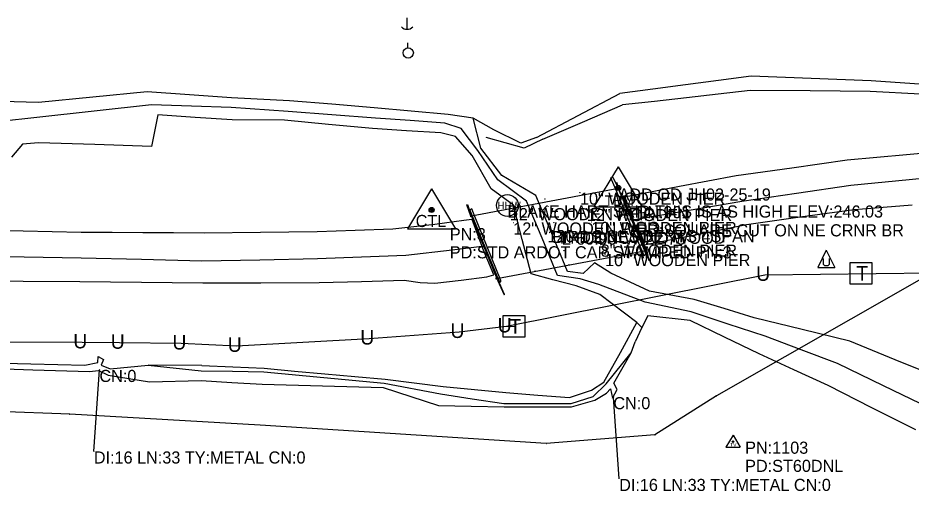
# Model space of a CAD drawing. Extents: x 1939239 to 1943096, y 531224 to 537447.
# Drawn here: x 1940668.9 to 1941037.4, y 534669 to 534864.3 of the extents above; entities that cross this region are included whole.
import ezdxf

# ---------------------------------------------------------------- set-up
doc = ezdxf.new("R2010")
doc.units = 0
for name, color, linetype in [('Default', 7, 'Continuous'), ('S_BRIDGE', 7, 'Continuous'), ('S_BRIDGE_ANNOT', 7, 'Continuous'), ('S_CROSS_DRAIN', 7, 'Continuous'), ('S_CROSS_DRAIN_ANNOT', 7, 'Continuous'), ('S_DITCHLINE', 7, 'Continuous'), ('S_DRG_PT_SYM', 7, 'Continuous'), ('S_EDGE_PAVEMENT', 7, 'Continuous'), ('S_HIST_HIGH_WATER', 7, 'Continuous'), ('S_HIST_HIGH_WATER_ANNOT', 7, 'Continuous'), ('S_MISC_STRUCTURES_ANNOT', 7, 'Continuous'), ('S_MSC_PT_SYM', 7, 'Continuous'), ('S_PAVEMENT_CROWN', 7, 'Continuous'), ('S_PRIMARY_CTL', 7, 'Continuous'), ('S_PRIMARY_CTL_ANNOT', 7, 'Continuous'), ('S_SECONDARY_CTL', 7, 'Continuous'), ('S_SECONDARY_CTL_ANNOT', 7, 'Continuous'), ('S_STR_PT_SYM', 7, 'Continuous'), ('S_SURVEY_TEXT_ANNOT', 7, 'Continuous'), ('S_TELEPHONE_UTILITIES', 7, 'Continuous'), ('S_UNDERGROUND_CABLE', 7, 'Continuous'), ('S_UTILITY_POLE', 7, 'Continuous'), ('S_UTL_PT_SYM', 7, 'Continuous'), ('S_WALL', 7, 'Continuous'), ('S_WATER_UTILITIES', 7, 'Continuous')]:
    doc.layers.add(name, color=color, linetype=linetype)

msp = doc.modelspace()

# ---------------------------------------------------------------- linework, layer by layer
at = {"layer": 'S_BRIDGE'}
for p, q in [((1940916.7, 534793.93), (1940855.99, 534782.52)), ((1940928.01, 534768.34), (1940916.7, 534793.93)), ((1940855.99, 534782.52), (1940866.42, 534756.81)), ((1940866.42, 534756.81), (1940928.01, 534768.34))]:
    msp.add_line(p, q, dxfattribs=at)
at = {"layer": 'S_CROSS_DRAIN'}
for p, q in [((1940700.2, 534685.38), (1940702.51, 534719.04)), ((1940916.92, 534674.06), (1940914.53, 534707.81))]:
    msp.add_line(p, q, dxfattribs=at)
at = {"layer": 'S_DITCHLINE'}
for points in [[(1941356.72, 534832.94), (1941356.86, 534833.91), (1941338.36, 534833.68), (1941319.86, 534833.44), (1941298.62, 534833.2), (1941277.38, 534832.97), (1941256.04, 534833.57), (1941234.71, 534834.18), (1941214.38, 534834.56), (1941194.04, 534834.93), (1941175.23, 534835.53), (1941156.41, 534836.12), (1941133.85, 534837.32), (1941111.3, 534838.52), (1941087.89, 534836.93), (1941064.48, 534835.33), (1941042.69, 534836.83), (1941020.9, 534838.32), (1940996.16, 534839.27), (1940971.42, 534840.22), (1940957.88, 534838.44), (1940944.34, 534836.67), (1940930.79, 534834.89), (1940917.25, 534833.11)], [(1941049.66, 534715.63), (1941030.84, 534723.24), (1941012.02, 534730.85), (1940992.35, 534735.7), (1940972.67, 534740.54), (1940960.27, 534744.33), (1940947.88, 534748.11), (1940929.43, 534751.52), (1940913.49, 534758.92), (1940906.72, 534763.16), (1940902.02, 534758.85), (1940895.66, 534759.68), (1940889.09, 534775.36), (1940882.53, 534791.03), (1940868.57, 534799.24), (1940859.9, 534810.49), (1940856.63, 534822.99), (1940846.33, 534824.51), (1940831.06, 534825.88), (1940815.8, 534827.24), (1940798.32, 534828.7), (1940780.85, 534830.15), (1940757, 534831.31), (1940739.62, 534832.53), (1940722.24, 534833.75), (1940699.8, 534831.6), (1940677.37, 534829.44), (1940662.29, 534829.82)], [(1940882.86, 534814.91), (1940900.06, 534824.01), (1940917.25, 534833.11)], [(1941356.66, 534832.31), (1941338.01, 534831.38), (1941319.37, 534830.45), (1941298.07, 534830.31), (1941276.77, 534830.18), (1941255.95, 534830.68), (1941235.14, 534831.17), (1941214.28, 534831.69), (1941193.41, 534832.21), (1941174.87, 534832.43), (1941156.32, 534832.65), (1941133.65, 534833.25), (1941110.99, 534833.85), (1941086.48, 534832.82), (1941061.97, 534831.78), (1941041.25, 534832.89), (1941020.53, 534834.01), (1940995.73, 534834.15), (1940970.92, 534834.29), (1940957.78, 534832.82), (1940944.63, 534831.35), (1940931.48, 534829.87), (1940918.33, 534828.4)], [(1941045.02, 534703.25), (1941026, 534712.47), (1941006.97, 534721.69), (1940992.06, 534727.32), (1940977.15, 534732.95), (1940961.91, 534737.97), (1940946.67, 534742.99), (1940927.62, 534747.04), (1940908.47, 534754.3), (1940900.87, 534756.68), (1940891.53, 534758.05), (1940885.14, 534773.37), (1940878.74, 534788.7), (1940866.82, 534797.46), (1940858.55, 534809.6), (1940851.74, 534818.65), (1940844.96, 534820.87), (1940830.66, 534821.93), (1940816.36, 534822.99), (1940798.33, 534824.31), (1940780.3, 534825.62), (1940756.86, 534827.33), (1940740.45, 534827.88), (1940724.04, 534828.42), (1940700.37, 534825.85), (1940676.71, 534823.27), (1940661.7, 534821.6)], [(1940885.36, 534814.2), (1940901.85, 534821.3), (1940918.33, 534828.4)], [(1941039.25, 534694.23), (1941021.19, 534703.39), (1941003.13, 534712.55), (1940988.93, 534719.08), (1940974.73, 534725.61), (1940960.44, 534732.49), (1940946.16, 534739.38), (1940928.75, 534741.4), (1940926.3, 534736.57), (1940924.19, 534738.53), (1940908.97, 534750.13), (1940899.12, 534753.8), (1940889.59, 534756.15), (1940880.57, 534758.73), (1940876.97, 534772.89), (1940873.38, 534787.05), (1940864.14, 534793.79), (1940856.34, 534807.59), (1940849.35, 534815.33), (1940843.39, 534816.83), (1940829.25, 534817.73), (1940815.11, 534818.63), (1940796.95, 534820.39), (1940778.79, 534822.15), (1940757.29, 534822.18), (1940741.96, 534823.26), (1940726.62, 534824.34), (1940724.02, 534811.28), (1940700.67, 534812.03), (1940677.33, 534812.78), (1940670.81, 534812.16), (1940666.3, 534806.81)], [(1940865.25, 534818.17), (1940856.63, 534822.99)], [(1940882.86, 534814.91), (1940876.29, 534812.65), (1940865.25, 534818.17)], [(1940885.36, 534814.2), (1940877.76, 534810.56), (1940862.03, 534814.92)], [(1940910.66, 534713.92), (1940917.42, 534726.23), (1940924.19, 534738.53)], [(1940926.3, 534736.57), (1940923.48, 534730.55)], [(1940651.98, 534722.03), (1940674.22, 534721.5), (1940696.47, 534720.96), (1940701.9, 534722.08), (1940702.01, 534724.54), (1940704.16, 534723.31), (1940703.16, 534720.94), (1940706.98, 534719.43), (1940722.63, 534720.97), (1940744.51, 534718.71), (1940757.43, 534718.48), (1940770.35, 534718.25), (1940795.15, 534715.93), (1940819.95, 534713.62), (1940843.22, 534709.12), (1940856.28, 534707.16), (1940869.33, 534705.2), (1940883.22, 534705.16), (1940897.11, 534705.11), (1940906.19, 534708.08), (1940911.56, 534713.24), (1940921.89, 534726.14), (1940923.48, 534730.55)], [(1940914.68, 534713.52), (1940921.89, 534726.14)], [(1940651.66, 534719.94), (1940675, 534719.13), (1940698.35, 534718.32), (1940702.14, 534718.83), (1940706.05, 534716.91), (1940723.16, 534714.1), (1940744.53, 534714.6), (1940757.07, 534713.85), (1940769.61, 534713.1), (1940794.57, 534712.45), (1940819.52, 534711.8), (1940842.41, 534704.34), (1940855.93, 534704.08), (1940869.44, 534703.81), (1940883.36, 534703.77), (1940897.29, 534703.73), (1940906.9, 534706.49), (1940911.72, 534709.49), (1940913.39, 534711.19), (1940914.17, 534707.43), (1940916.06, 534711.01), (1940914.68, 534713.52)], [(1940744.69, 534720.82), (1940722.63, 534720.97)], [(1940744.69, 534720.82), (1940757.58, 534720.26), (1940770.47, 534719.7), (1940782.95, 534718.57), (1940795.43, 534717.43), (1940807.91, 534716.3), (1940820.39, 534715.17), (1940844.25, 534712.15), (1940857.22, 534710.9), (1940870.2, 534709.66), (1940883.31, 534708.67), (1940896.42, 534707.68), (1940905.57, 534710.7), (1940910.66, 534713.92)]]:
    msp.add_lwpolyline(points, dxfattribs=at)
at = {"layer": 'S_DRG_PT_SYM'}
for points in [[(1940702.51, 534719.04), (1940702.51, 534719.09), (1940702.51, 534719.04), (1940702.46, 534719.04), (1940702.51, 534719.04), (1940702.51, 534718.99), (1940702.51, 534719.04), (1940702.56, 534719.04)], [(1940914.53, 534707.81), (1940914.53, 534707.86), (1940914.53, 534707.81), (1940914.48, 534707.81), (1940914.53, 534707.81), (1940914.53, 534707.76), (1940914.53, 534707.81), (1940914.58, 534707.81)], [(1940700.2, 534685.38), (1940700.2, 534685.43), (1940700.2, 534685.38), (1940700.15, 534685.38), (1940700.2, 534685.38), (1940700.2, 534685.33), (1940700.2, 534685.38), (1940700.25, 534685.38)], [(1940916.92, 534674.06), (1940916.92, 534674.11), (1940916.92, 534674.06), (1940916.87, 534674.06), (1940916.92, 534674.06), (1940916.92, 534674.01), (1940916.92, 534674.06), (1940916.97, 534674.06)]]:
    msp.add_lwpolyline(points, dxfattribs=at)
at = {"layer": 'S_EDGE_PAVEMENT'}
for points in [[(1940918.46, 534790.36), (1940941.8, 534794.81), (1940965.15, 534799.25), (1940988.1, 534802.49), (1941011.04, 534805.72), (1941035.48, 534807.92), (1941059.93, 534810.12)], [(1940918.46, 534790.36), (1940922.58, 534780.98)], [(1940927.18, 534770.6), (1940948.3, 534774.85), (1940969.42, 534779.09), (1940991.65, 534782.15), (1941013.88, 534785.21), (1941037.83, 534787.17)], [(1940647.14, 534776.84), (1940671.09, 534776.39), (1940695.04, 534775.95), (1940707.71, 534775.87), (1940720.38, 534775.8), (1940733.06, 534775.73), (1940745.73, 534775.66), (1940769.02, 534775.88), (1940792.32, 534776.1), (1940807.94, 534776.69), (1940823.56, 534777.27), (1940840.91, 534779.15), (1940852.87, 534780.9), (1940856.11, 534781.19)], [(1940856.11, 534781.19), (1940860.29, 534770.05)], [(1940927.18, 534770.6), (1940922.58, 534780.98)], [(1940865.21, 534758.31), (1940860.29, 534770.05)], [(1940647.55, 534755.91), (1940671.01, 534755.72), (1940694.46, 534755.53), (1940707.14, 534755.39), (1940719.83, 534755.24), (1940732.52, 534755.09), (1940745.2, 534754.95), (1940769.16, 534755.02), (1940793.12, 534755.09), (1940810.66, 534755.57), (1940828.2, 534756.05), (1940834.85, 534755.15), (1940840.83, 534754.78), (1940851.7, 534756.09), (1940862.27, 534757.47), (1940865.21, 534758.31)]]:
    msp.add_lwpolyline(points, dxfattribs=at)
at = {"layer": 'S_HIST_HIGH_WATER'}
msp.add_circle((1940870.81, 534786.91), 4.5, dxfattribs=at)
at = {"layer": 'S_MSC_PT_SYM'}
for points in [[(1940900.75, 534792.23), (1940900.75, 534792.28), (1940900.75, 534792.23), (1940900.7, 534792.23), (1940900.75, 534792.23), (1940900.75, 534792.18), (1940900.75, 534792.23), (1940900.8, 534792.23)], [(1940886.32, 534789.62), (1940886.32, 534789.67), (1940886.32, 534789.62), (1940886.27, 534789.62), (1940886.32, 534789.62), (1940886.32, 534789.57), (1940886.32, 534789.62), (1940886.37, 534789.62)], [(1940871.83, 534785.81), (1940871.83, 534785.86), (1940871.83, 534785.81), (1940871.78, 534785.81), (1940871.83, 534785.81), (1940871.83, 534785.76), (1940871.83, 534785.81), (1940871.88, 534785.81)], [(1940887.61, 534786.36), (1940887.61, 534786.41), (1940887.61, 534786.36), (1940887.56, 534786.36), (1940887.61, 534786.36), (1940887.61, 534786.31), (1940887.61, 534786.36), (1940887.66, 534786.36)], [(1940903.56, 534785.47), (1940903.56, 534785.52), (1940903.56, 534785.47), (1940903.51, 534785.47), (1940903.56, 534785.47), (1940903.56, 534785.42), (1940903.56, 534785.47), (1940903.61, 534785.47)], [(1940873.23, 534779.89), (1940873.23, 534779.94), (1940873.23, 534779.89), (1940873.18, 534779.89), (1940873.23, 534779.89), (1940873.23, 534779.84), (1940873.23, 534779.89), (1940873.28, 534779.89)], [(1940890.02, 534779.93), (1940890.02, 534779.98), (1940890.02, 534779.93), (1940889.97, 534779.93), (1940890.02, 534779.93), (1940890.02, 534779.88), (1940890.02, 534779.93), (1940890.07, 534779.93)], [(1940905.43, 534780.14), (1940905.43, 534780.19), (1940905.43, 534780.14), (1940905.38, 534780.14), (1940905.43, 534780.14), (1940905.43, 534780.09), (1940905.43, 534780.14), (1940905.48, 534780.14)], [(1940887.33, 534776.75), (1940887.33, 534776.8), (1940887.33, 534776.75), (1940887.28, 534776.75), (1940887.33, 534776.75), (1940887.33, 534776.7), (1940887.33, 534776.75), (1940887.38, 534776.75)], [(1940889.3, 534776.41), (1940889.3, 534776.46), (1940889.3, 534776.41), (1940889.25, 534776.41), (1940889.3, 534776.41), (1940889.3, 534776.36), (1940889.3, 534776.41), (1940889.35, 534776.41)], [(1940891.27, 534776.07), (1940891.27, 534776.12), (1940891.27, 534776.07), (1940891.22, 534776.07), (1940891.27, 534776.07), (1940891.27, 534776.02), (1940891.27, 534776.07), (1940891.32, 534776.07)], [(1940891.83, 534774.13), (1940891.83, 534774.18), (1940891.83, 534774.13), (1940891.78, 534774.13), (1940891.83, 534774.13), (1940891.83, 534774.08), (1940891.83, 534774.13), (1940891.88, 534774.13)], [(1940893.24, 534775.72), (1940893.24, 534775.77), (1940893.24, 534775.72), (1940893.19, 534775.72), (1940893.24, 534775.72), (1940893.24, 534775.67), (1940893.24, 534775.72), (1940893.29, 534775.72)], [(1940875.8, 534773.26), (1940875.8, 534773.31), (1940875.8, 534773.26), (1940875.75, 534773.26), (1940875.8, 534773.26), (1940875.8, 534773.21), (1940875.8, 534773.26), (1940875.85, 534773.26)], [(1940908.08, 534773.63), (1940908.08, 534773.68), (1940908.08, 534773.63), (1940908.03, 534773.63), (1940908.08, 534773.63), (1940908.08, 534773.58), (1940908.08, 534773.63), (1940908.13, 534773.63)], [(1940909.31, 534770.77), (1940909.31, 534770.82), (1940909.31, 534770.77), (1940909.26, 534770.77), (1940909.31, 534770.77), (1940909.31, 534770.72), (1940909.31, 534770.77), (1940909.36, 534770.77)], [(1940878.13, 534768.21), (1940878.13, 534768.26), (1940878.13, 534768.21), (1940878.08, 534768.21), (1940878.13, 534768.21), (1940878.13, 534768.16), (1940878.13, 534768.21), (1940878.18, 534768.21)], [(1940894.13, 534768.27), (1940894.13, 534768.32), (1940894.13, 534768.27), (1940894.08, 534768.27), (1940894.13, 534768.27), (1940894.13, 534768.22), (1940894.13, 534768.27), (1940894.18, 534768.27)], [(1940911.1, 534766.85), (1940911.1, 534766.9), (1940911.1, 534766.85), (1940911.05, 534766.85), (1940911.1, 534766.85), (1940911.1, 534766.8), (1940911.1, 534766.85), (1940911.15, 534766.85)], [(1940880.47, 534762.81), (1940880.47, 534762.86), (1940880.47, 534762.81), (1940880.42, 534762.81), (1940880.47, 534762.81), (1940880.47, 534762.76), (1940880.47, 534762.81), (1940880.52, 534762.81)], [(1940882.23, 534759.85), (1940882.23, 534759.9), (1940882.23, 534759.85), (1940882.18, 534759.85), (1940882.23, 534759.85), (1940882.23, 534759.8), (1940882.23, 534759.85), (1940882.28, 534759.85)], [(1940896.15, 534762.45), (1940896.15, 534762.5), (1940896.15, 534762.45), (1940896.1, 534762.45), (1940896.15, 534762.45), (1940896.15, 534762.4), (1940896.15, 534762.45), (1940896.2, 534762.45)]]:
    msp.add_lwpolyline(points, dxfattribs=at)
at = {"layer": 'S_PAVEMENT_CROWN'}
for points in [[(1940922.58, 534780.98), (1940945.02, 534784.82), (1940967.46, 534788.66), (1940990.01, 534791.94), (1941012.55, 534795.22), (1941036.52, 534797.59), (1941060.48, 534799.96)], [(1940647.87, 534765.97), (1940671.43, 534765.66), (1940694.99, 534765.34), (1940719.89, 534764.69), (1940744.8, 534764.04), (1940768.62, 534764.51), (1940792.45, 534764.97), (1940810.66, 534765.67), (1940828.88, 534766.37), (1940847.99, 534768.6), (1940860.29, 534770.05)]]:
    msp.add_lwpolyline(points, dxfattribs=at)
at = {"layer": 'S_PRIMARY_CTL'}
for p, q in [((1940916.55, 534802.84), (1940906.52, 534786.33)), ((1940916.55, 534802.84), (1940926.38, 534786.33)), ((1940839.56, 534793.77), (1940829.53, 534777.26)), ((1940839.56, 534793.77), (1940849.39, 534777.26)), ((1940906.52, 534786.33), (1940926.38, 534786.33)), ((1940829.53, 534777.26), (1940849.39, 534777.26))]:
    msp.add_line(p, q, dxfattribs=at)
for centre, radius in [((1940916.55, 534794.14), 1.04), ((1940916.55, 534794.14), 0.609), ((1940916.55, 534794.14), 0.344), ((1940839.56, 534785.07), 1.04), ((1940839.56, 534785.07), 0.609), ((1940839.56, 534785.07), 0.344)]:
    msp.add_circle(centre, radius, dxfattribs=at)
at = {"layer": 'S_SECONDARY_CTL'}
for p, q in [((1940963.89, 534692.04), (1940960.88, 534687.09)), ((1940963.89, 534692.04), (1940966.83, 534687.09)), ((1940960.88, 534687.09), (1940966.83, 534687.09))]:
    msp.add_line(p, q, dxfattribs=at)
for radius in [0.311, 0.183, 0.103]:
    msp.add_circle((1940963.89, 534689.43), radius, dxfattribs=at)
at = {"layer": 'S_STR_PT_SYM'}
for points in [[(1940916.7, 534793.93), (1940916.7, 534794.43), (1940916.7, 534793.93), (1940916.2, 534793.93), (1940916.7, 534793.93), (1940916.7, 534793.43), (1940916.7, 534793.93), (1940917.2, 534793.93)], [(1940855.99, 534782.52), (1940855.99, 534783.02), (1940855.99, 534782.52), (1940855.49, 534782.52), (1940855.99, 534782.52), (1940855.99, 534782.02), (1940855.99, 534782.52), (1940856.49, 534782.52)], [(1940928.01, 534768.34), (1940928.01, 534768.84), (1940928.01, 534768.34), (1940927.51, 534768.34), (1940928.01, 534768.34), (1940928.01, 534767.84), (1940928.01, 534768.34), (1940928.51, 534768.34)], [(1940866.42, 534756.81), (1940866.42, 534757.31), (1940866.42, 534756.81), (1940865.92, 534756.81), (1940866.42, 534756.81), (1940866.42, 534756.31), (1940866.42, 534756.81), (1940866.92, 534756.81)]]:
    msp.add_lwpolyline(points, dxfattribs=at)
at = {"layer": 'S_TELEPHONE_UTILITIES'}
for points in [[(1941012.15, 534754.36), (1941012.15, 534763.36), (1941021.15, 534763.36), (1941021.15, 534754.36)], [(1940869.05, 534732.48), (1940869.05, 534741.48), (1940878.05, 534741.48), (1940878.05, 534732.48)]]:
    msp.add_lwpolyline(points, close=True, dxfattribs=at)
at = {"layer": 'S_UNDERGROUND_CABLE'}
for p, q in [((1941002.37, 534768.44), (1940998.84, 534761.35)), ((1941002.37, 534768.44), (1941005.86, 534761.35)), ((1941001.17, 534762.59), (1941001.17, 534765.03)), ((1941003.53, 534765.03), (1941003.53, 534762.59)), ((1940977.05, 534758.32), (1941046.29, 534759.1)), ((1940998.84, 534761.35), (1941005.86, 534761.35)), ((1941001.79, 534761.93), (1941001.17, 534762.59)), ((1941002.99, 534761.93), (1941001.79, 534761.93)), ((1941003.53, 534762.59), (1941002.99, 534761.93)), ((1940870.42, 534737.03), (1940977.05, 534758.32)), ((1940850.94, 534734.75), (1940870.42, 534737.03)), ((1940870.42, 534737.03), (1940873.78, 534736.99)), ((1940813.74, 534732.04), (1940850.94, 534734.75)), ((1940659.05, 534730.68), (1940695.34, 534730.46)), ((1940695.34, 534730.46), (1940710.78, 534730.31)), ((1940710.78, 534730.31), (1940736.23, 534730)), ((1940736.23, 534730), (1940759.07, 534729.02)), ((1940759.07, 534729.02), (1940813.74, 534732.04))]:
    msp.add_line(p, q, dxfattribs=at)
at = {"layer": 'S_UTILITY_POLE'}
for p, q in [((1940829.36, 534864.34), (1940829.36, 534859.61)), ((1940829.77, 534851.98), (1940829.77, 534854.09))]:
    msp.add_line(p, q, dxfattribs=at)
msp.add_circle((1940829.89, 534849.84), 2.13, dxfattribs=at)
msp.add_arc((1940829.42, 534863.04), 3.41, 226.3972, 313.6028, dxfattribs=at)
at = {"layer": 'S_UTL_PT_SYM'}
for points in [[(1940957.11, 534708.35), (1940957.11, 534708.4), (1940957.11, 534708.35), (1940957.06, 534708.35), (1940957.11, 534708.35), (1940957.11, 534708.3), (1940957.11, 534708.35), (1940957.16, 534708.35)], [(1940690.26, 534700.72), (1940690.26, 534700.77), (1940690.26, 534700.72), (1940690.21, 534700.72), (1940690.26, 534700.72), (1940690.26, 534700.67), (1940690.26, 534700.72), (1940690.31, 534700.72)], [(1940768.8, 534696.26), (1940768.8, 534696.31), (1940768.8, 534696.26), (1940768.75, 534696.26), (1940768.8, 534696.26), (1940768.8, 534696.21), (1940768.8, 534696.26), (1940768.85, 534696.26)], [(1940931.69, 534692.18), (1940931.69, 534692.23), (1940931.69, 534692.18), (1940931.64, 534692.18), (1940931.69, 534692.18), (1940931.69, 534692.13), (1940931.69, 534692.18), (1940931.74, 534692.18)], [(1940886.86, 534688.64), (1940886.86, 534688.69), (1940886.86, 534688.64), (1940886.81, 534688.64), (1940886.86, 534688.64), (1940886.86, 534688.59), (1940886.86, 534688.64), (1940886.91, 534688.64)]]:
    msp.add_lwpolyline(points, dxfattribs=at)
at = {"layer": 'S_WALL'}
for points in [[(1940915.15, 534794.51), (1940913.48, 534798.24), (1940914.27, 534798.6), (1940915.97, 534795.16)], [(1940926.78, 534767.27), (1940920.96, 534780.89), (1940915.15, 534794.51)], [(1940915.97, 534795.16), (1940921.94, 534781.03), (1940927.91, 534766.89)], [(1940856.84, 534783.73), (1940856.12, 534785.45), (1940855.33, 534785.13), (1940855.9, 534783.54)], [(1940855.9, 534783.54), (1940861.54, 534769.87), (1940867.19, 534756.2)], [(1940868.09, 534755.98), (1940862.47, 534769.86), (1940856.84, 534783.73)], [(1940927.91, 534766.89), (1940928.03, 534766.63), (1940927.16, 534766.36), (1940926.78, 534767.27)], [(1940866.96, 534756.12), (1940866.72, 534756.07), (1940869.42, 534750.06), (1940869.68, 534750.2)], [(1940869.68, 534750.2), (1940866.96, 534756.12)], [(1940867.19, 534756.2), (1940867.63, 534755.26), (1940868.12, 534755.44), (1940868.09, 534755.98)]]:
    msp.add_lwpolyline(points, dxfattribs=at)
for points in [[(1940916.21, 534795.04), (1940916.42, 534795.19), (1940915.93, 534796.32), (1940915.7, 534796.17)], [(1940856, 534782.48), (1940855.71, 534782.45), (1940854.06, 534787.19), (1940854.29, 534787.28)], [(1940928.35, 534768.58), (1940928.17, 534768.38), (1940929.11, 534764.05), (1940929.3, 534764.16)]]:
    msp.add_lwpolyline(points, close=True, dxfattribs=at)
at = {"layer": 'S_WATER_UTILITIES'}
for p, q in [((1941040.71, 534756.11), (1940957.11, 534708.35)), ((1940957.11, 534708.35), (1940931.69, 534692.18)), ((1940690.26, 534700.72), (1940587.78, 534704.58)), ((1940768.8, 534696.26), (1940690.26, 534700.72)), ((1940886.86, 534688.64), (1940768.8, 534696.26)), ((1940931.69, 534692.18), (1940886.86, 534688.64))]:
    msp.add_line(p, q, dxfattribs=at)

# ---------------------------------------------------------------- texts
at = {"layer": 'Default'}
for p in [(1940973.42, 534755.78), (1940847.31, 534732.2), (1940866.79, 534734.49), (1940691.71, 534727.92), (1940707.15, 534727.76), (1940732.6, 534727.46), (1940810.11, 534729.49), (1940755.44, 534726.47)]:
    msp.add_text('U', height=6, dxfattribs=at).set_placement(p)
at = {"layer": 'S_BRIDGE_ANNOT'}
msp.add_text('ADD OD JH02-25-19', height=5, dxfattribs=at).set_placement((1940916.7, 534788.93))
at = {"layer": 'S_CROSS_DRAIN_ANNOT'}
for s, p in [('CN:0', (1940702.51, 534714.04)), ('CN:0', (1940914.53, 534702.81)), ('DI:16 LN:33 TY:METAL CN:0', (1940700.2, 534680.38)), ('DI:16 LN:33 TY:METAL CN:0', (1940916.92, 534669.06))]:
    msp.add_text(s, height=5, dxfattribs=at).set_placement(p)
at = {"layer": 'S_HIST_HIGH_WATER'}
msp.add_text('HHW', height=3, dxfattribs=at).set_placement((1940866.72, 534785.41))
at = {"layer": 'S_HIST_HIGH_WATER_ANNOT'}
msp.add_text('BLAKE HART SAID THIS IS AS HIGH ELEV:246.03', height=5, dxfattribs=at).set_placement((1940870.81, 534781.91))
at = {"layer": 'S_MISC_STRUCTURES_ANNOT'}
for s, p in [('10" WOODEN PIER', (1940900.75, 534787.23)), ('12" WOODEN PEIR', (1940871.83, 534780.81)), ('12" WOODEN PIER', (1940903.56, 534780.47)), ('12" WOODEN PIER', (1940873.23, 534774.89)), ('10" WOODEN PIER', (1940905.43, 534775.14)), ('8" WOODEN PIER', (1940909.31, 534765.77)), ('10" WOODEN PIER', (1940911.1, 534761.85))]:
    msp.add_text(s, height=5, dxfattribs=at).set_placement(p)
at = {"layer": 'S_PRIMARY_CTL'}
for s, height, p in [('TBM', 4.287, (1940910.9, 534786.75)), ('CTL', 5, (1940832.98, 534778))]:
    msp.add_text(s, height=height, dxfattribs=at).set_placement(p)
at = {"layer": 'S_PRIMARY_CTL_ANNOT'}
for s, p in [('PN:901', (1940924.05, 534781.64)), ('PN:3', (1940847.06, 534772.57)), ('PD:SQUARE CUT ON NE CRNR BR', (1940924.05, 534774.14)), ('PD:STD ARDOT CAP STAMPED PN:3', (1940847.06, 534765.07))]:
    msp.add_text(s, height=5, dxfattribs=at).set_placement(p)
at = {"layer": 'S_SECONDARY_CTL'}
msp.add_text('TV', height=1.5, dxfattribs=at).set_placement((1940962.68, 534687.42))
at = {"layer": 'S_SECONDARY_CTL_ANNOT'}
for s, p in [('PN:1103', (1940968.89, 534684.43)), ('PD:ST60DNL', (1940968.89, 534676.93))]:
    msp.add_text(s, height=5, dxfattribs=at).set_placement(p)
at = {"layer": 'S_SURVEY_TEXT_ANNOT'}
for s, p in [('120-1 2.61 5 BENTS 4SPAN', (1940887.33, 534771.75)), ('BIRDS NEST', (1940889.3, 534771.41)), ('TY CONC AND WOOD', (1940891.27, 534771.07)), ("L-60.90' W-22.75'", (1940893.24, 534770.72))]:
    msp.add_text(s, height=5, dxfattribs=at).set_placement(p)
at = {"layer": 'S_TELEPHONE_UTILITIES'}
for p in [(1941014.71, 534755.86), (1940871.62, 534733.98)]:
    msp.add_text('T', height=6, dxfattribs=at).set_placement(p)

doc.saveas('drawing.dxf')
